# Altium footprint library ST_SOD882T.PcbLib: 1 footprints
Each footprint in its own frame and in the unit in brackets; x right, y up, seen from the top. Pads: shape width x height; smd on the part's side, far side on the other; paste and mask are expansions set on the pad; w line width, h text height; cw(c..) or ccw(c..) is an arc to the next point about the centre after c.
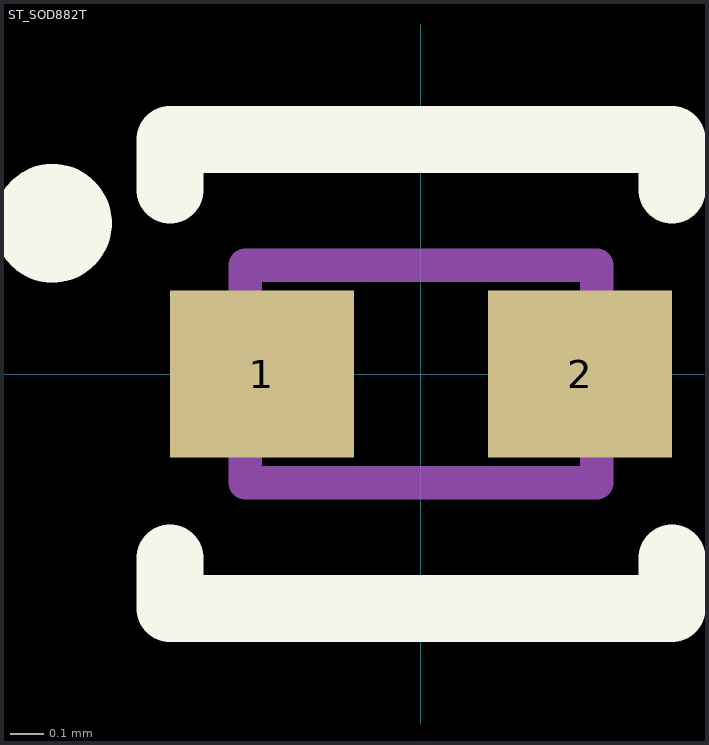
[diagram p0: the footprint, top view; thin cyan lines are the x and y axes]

## ST_SOD882T [mm]
height 0.4
pads (2):
  rect 0.55x0.5 smd paste-0.05: 1(-0.475,0) 2(0.475,0)
Top Overlay:
  circle w0.254: c-1.1,0.45 r0.05
  lines w0.2: -0.75,-0.55 -0.75,-0.7 0.75,-0.7 0.75,-0.55 ; -0.75,0.55 -0.75,0.7 0.75,0.7 0.75,0.55
Mechanical 13:
  lines w0.1: -0.525,-0.325 0.525,-0.325 0.525,0.325 -0.525,0.325 -0.525,-0.325
3D body "ST_SOD882TB.step": height 0.4, standoff 0, extent -0.525,-0.325 0.525,0.325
